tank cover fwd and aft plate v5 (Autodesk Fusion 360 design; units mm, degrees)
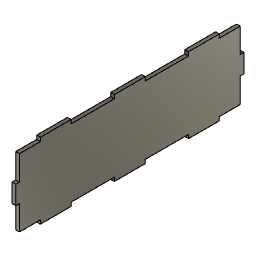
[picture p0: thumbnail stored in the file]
sketch "Sketch1" plane through (0, 0, 0) normal (1, 0, 0) x axis (0, 1, 0)
  line L1 (-92.5, -30.5) -> (92.5, -30.5)
  line L2 (-92.5, 30.5) -> (-92.5, -30.5)
  line L3 (92.5, 30.5) -> (-92.5, 30.5)
  line L4 (92.5, -30.5) -> (92.5, 30.5)
  line L5 (-92.5, 30.5) -> (92.5, -30.5)
  line L6 (92.5, 30.5) -> (-92.5, -30.5)
  point P6 (0, 0)
  point P1 (0, 0)
  point P4 (-92.5, 30.5)
  point P5 (92.5, 30.5)
  point P3 (-92.5, -30.5)
  perpendicular L1 L2
  parallel L1 L3
  parallel L2 L4
  horizontal L1
  coincident L5 P6
  coincident L6 P6
  coincident P1 P6
  dimension "d1" distance P4 P5 = 185
  dimension "d2" distance P3 P4 = 61
extrude "Extrude1" new body sketch "Sketch1" profile of L1 L2 L3 L4 along normal blind 3
sketch "Sketch2" plane through (3, 0, 0) normal (1, 0, 0) x axis (0, 1, 0)
  line L1 (-92.5, 30.5) -> (92.5, 30.5)
  line L2 (-92.5, -30.5) -> (-92.5, 30.5)
  line L3 (92.5, -30.5) -> (-92.5, -30.5)
  line L4 (92.5, 30.5) -> (92.5, -30.5)
  line L5 (-89.5, 30.5) -> (-92.5, 30.5)
  line L6 (-89.5, 7.5) -> (-89.5, 30.5)
  line L7 (-92.5, 7.5) -> (-89.5, 7.5)
  line L8 (-92.5, 30.5) -> (-92.5, 7.5)
  line L9 (-89.5, -30.5) -> (-92.5, -30.5)
  line L10 (-89.5, -7.5) -> (-89.5, -30.5)
  line L11 (-92.5, -7.5) -> (-89.5, -7.5)
  line L12 (-92.5, -30.5) -> (-92.5, -7.5)
  point P3 (-92.5, 30.5)
  point P6 (-92.5, 30.5)
  point P4 (-92.5, -30.5)
  point P10 (-92.5, -30.5)
  point P9 (-92.5, 7.5)
  point P13 (-92.5, -7.5)
  horizontal L5
  vertical L6
  horizontal L7
  vertical L8
  coincident P3 P6
  horizontal L9
  vertical L10
  horizontal L11
  vertical L12
  coincident P4 P10
  dimension "d5" distance L10 L12 = 3
  dimension "d6" distance L6 L8 = 3
  dimension "d7" distance P6 P9 = 23
  dimension "d8" distance P10 P13 = 23
extrude "Extrude2" cut sketch "Sketch2" profile of L1 L2 L3 L5 L6 L7 L8 L9 L10 L11 L12 against normal blind 20
mirror "Mirror1"
sketch "Sketch3" plane through (3, 0, 0) normal (1, 0, 0) x axis (0, 1, 0)
  line L1 (-72.5, -30.5) -> (-89.5, -30.5)
  line L2 (-72.5, -27.5) -> (-72.5, -30.5)
  line L3 (-89.5, -27.5) -> (-72.5, -27.5)
  line L4 (-89.5, -30.5) -> (-89.5, -27.5)
  line L5 (89.5, -30.5) -> (-89.5, -30.5)
  line L6 (-12.5, -30.5) -> (-47.5, -30.5)
  line L7 (-12.5, -27.5) -> (-12.5, -30.5)
  line L8 (-47.5, -27.5) -> (-12.5, -27.5)
  line L9 (-47.5, -30.5) -> (-47.5, -27.5)
  line L10 (47.5, -30.5) -> (12.5, -30.5)
  line L11 (47.5, -27.5) -> (47.5, -30.5)
  line L12 (12.5, -27.5) -> (47.5, -27.5)
  line L13 (12.5, -30.5) -> (12.5, -27.5)
  line L14 (89.5, -30.5) -> (72.5, -30.5)
  line L15 (89.5, -27.5) -> (89.5, -30.5)
  line L16 (72.5, -27.5) -> (89.5, -27.5)
  line L17 (72.5, -30.5) -> (72.5, -27.5)
  line L18 (89.5, -7.5) -> (89.5, -30.5)
  line L19 (-89.5, -30.5) -> (-89.5, -7.5)
  line L20 (-92.5, -7.5) -> (-92.5, 7.5)
  line L21 (92.5, 7.5) -> (92.5, -7.5)
  point P8 (-47.5, -30.5)
  point P12 (12.5, -30.5)
  point P16 (72.5, -30.5)
  point P9 (-12.5, -30.5)
  point P13 (47.5, -30.5)
  point P3 (-72.5, -30.5)
  horizontal L1
  vertical L2
  horizontal L3
  vertical L4
  collinear L1 L5
  horizontal L6
  vertical L7
  horizontal L8
  vertical L9
  coincident L5 P8
  horizontal L10
  vertical L11
  horizontal L12
  vertical L13
  coincident L5 P12
  horizontal L14
  vertical L15
  horizontal L16
  vertical L17
  coincident L5 P16
  collinear L15 L18
  collinear L4 L19
  equal L13 L17
  equal L9 L13
  equal L2 L9
  dimension "d23" distance L1 L3 = 3
  dimension "d25" distance L2 L20 = 20
  dimension "d28" distance P16 L21 = 20
  dimension "d30" distance P8 P9 = 35
  dimension "d32" distance P12 P13 = 35
  dimension "d33" distance P13 P16 = 25
  dimension "d34" distance P3 P8 = 25
  dimension "d35" distance P9 P12 = 25
extrude "Extrude3" cut sketch "Sketch3" profile of L1 L2 L3 L4 L5 L6 L7 L8 L9 L10 L11 L12 L13 L14 L15 L16 L17 L18 L19 against normal blind 60
mirror "Mirror2"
